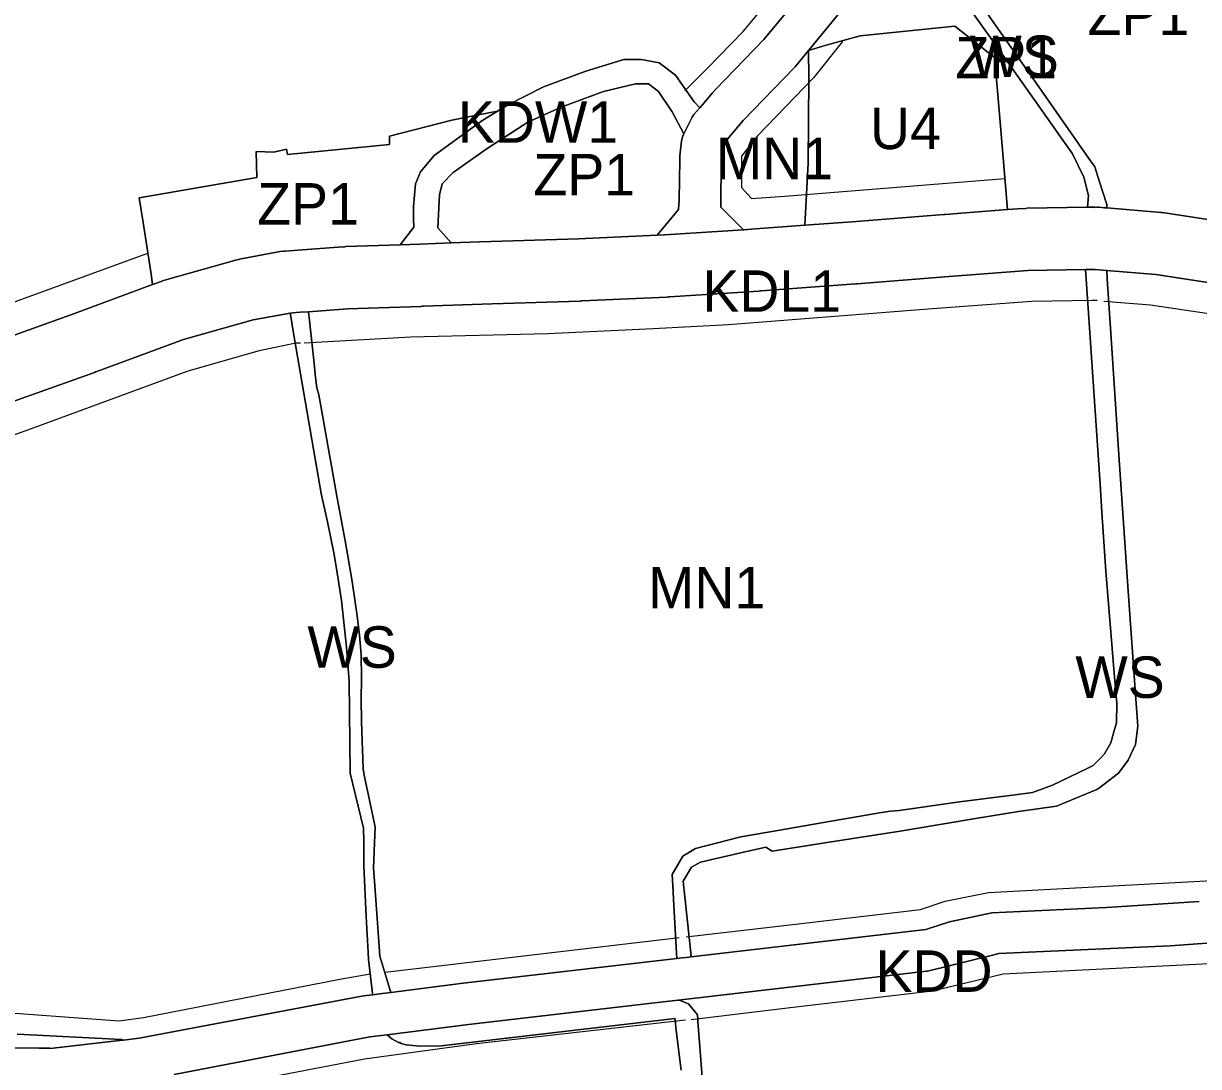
# Model space of a CAD drawing. Extents: x -284239 to -281592, y 34477 to 37267.
# Drawn here: x -282826.9 to -282543.7, y 34838 to 35089.5 of the extents above; entities that cross this region are included whole.
import ezdxf

# ---------------------------------------------------------------- set-up
doc = ezdxf.new("R2010")
doc.units = 0
for name, color, linetype in [('linie_rozgraniczajace', 7, 'Continuous'), ('linie_zabudowy_nieprzekraczalne', 7, 'Continuous'), ('oznaczenia_przeznaczen', 7, 'Continuous')]:
    doc.layers.add(name, color=color, linetype=linetype)

msp = doc.modelspace()

# ---------------------------------------------------------------- linework, layer by layer
at = {"layer": 'linie_rozgraniczajace'}
for points in [[(-282538.772, 35041.859), (-282551.853, 35043.871), (-282552.485, 35043.919), (-282552.668, 35043.964), (-282565.789, 35045.041), (-282565.808, 35045.885), (-282567.621, 35051.609), (-282568.68, 35054.953), (-282570.111, 35056.996), (-282581.07, 35072.638), (-282596.617, 35094.828), (-282609.755, 35113.582), (-282611.572, 35116.175), (-282614.042, 35117.421), (-282613.08, 35119.3), (-282610.133, 35128.196), (-282610.093, 35128.446), (-282609.945, 35128.969), (-282609.48, 35131.862), (-282600.308, 35133.065), (-282582.987, 35130.277), (-282556.202, 35125.799), (-282541.458, 35123.137)], [(-282636.922, 35099.643), (-282648.507, 35085.628), (-282660.041, 35073.649), (-282660.748, 35072.912), (-282660.948, 35072.694), (-282662.897, 35070.406), (-282663.908, 35069.219), (-282665.305, 35070.667), (-282669.735, 35077.066), (-282673.673, 35080.019), (-282677.938, 35080.84), (-282682.204, 35080.84), (-282691.392, 35078.05), (-282701.564, 35074.277), (-282710.26, 35069.847), (-282712.69, 35068.377), (-282717.657, 35067.445), (-282723.695, 35066.188), (-282738.74, 35062.356), (-282738.74, 35060.369), (-282763.295, 35057.956), (-282763.579, 35059.233), (-282766.56, 35058.524), (-282770.818, 35058.666), (-282770.676, 35052.42), (-282799.063, 35047.453), (-282798.07, 35041.491), (-282796.151, 35029.084), (-282795.832, 35026.541), (-282814.671, 35019.595), (-282837.032, 35011.566)], [(-282668.901, 35047.034), (-282668.738, 35056.643), (-282668.728, 35057.133), (-282668.702, 35057.574), (-282668.467, 35059.747), (-282668.32, 35061.107), (-282667.968, 35062.483), (-282667.876, 35062.622), (-282667.844, 35062.76), (-282667.767, 35062.918), (-282666.029, 35066.484), (-282665.714, 35066.927), (-282665.341, 35067.537), (-282663.908, 35069.219), (-282662.897, 35070.406), (-282660.948, 35072.694), (-282660.748, 35072.912), (-282660.041, 35073.649), (-282648.507, 35085.628), (-282636.922, 35099.643)], [(-282601.055, 35096.293), (-282592.555, 35084.274), (-282574.041, 35058.096), (-282571.344, 35052.434), (-282570.211, 35048.055), (-282570.476, 35045.195), (-282585.089, 35044.976), (-282585.653, 35044.859), (-282586.085, 35044.928), (-282589.712, 35044.647), (-282591.028, 35060.038), (-282592.158, 35073.29), (-282592.877, 35081.302), (-282602.43, 35088.904), (-282625.235, 35086.541), (-282633.479, 35084.274), (-282637.707, 35082.998), (-282637.614, 35083.111), (-282629.078, 35093.436)], [(-282596.617, 35094.828), (-282581.07, 35072.638), (-282570.111, 35056.996), (-282568.68, 35054.953), (-282567.621, 35051.609), (-282565.808, 35045.885), (-282565.789, 35045.041), (-282566.389, 35045.09), (-282567.683, 35045.196), (-282568.152, 35045.216), (-282568.414, 35045.163), (-282568.715, 35045.221), (-282568.756, 35045.22), (-282570.476, 35045.195), (-282570.211, 35048.055), (-282571.344, 35052.434), (-282574.041, 35058.096), (-282592.555, 35084.274), (-282601.055, 35096.293)], [(-282629.078, 35093.436), (-282637.614, 35083.111), (-282637.707, 35082.998), (-282640.92, 35079.111), (-282641.166, 35078.838), (-282653.434, 35066.093), (-282657.317, 35061.535), (-282658.472, 35059.165), (-282658.736, 35056.724), (-282658.852, 35045.263), (-282653.355, 35039.783), (-282672.385, 35038.548), (-282674.156, 35038.466), (-282669.063, 35044.635), (-282668.901, 35047.034)], [(-282837.032, 35011.566), (-282814.671, 35019.595), (-282795.832, 35026.541), (-282793.481, 35027.408), (-282793.409, 35027.421), (-282792.651, 35027.684), (-282775.484, 35032.544), (-282775.106, 35032.596), (-282774.505, 35032.774), (-282765.096, 35034.508), (-282764.222, 35034.588), (-282763.97, 35034.648), (-282750.06, 35035.661), (-282749.715, 35035.606), (-282749.253, 35035.706), (-282736.104, 35036.152), (-282731.441, 35036.31), (-282723.81, 35036.586), (-282714.78, 35036.912), (-282714.537, 35036.868), (-282714.25, 35036.93), (-282693.162, 35037.592), (-282674.156, 35038.466), (-282672.385, 35038.548), (-282653.355, 35039.783), (-282650.478, 35039.97), (-282638.574, 35040.847), (-282627.184, 35041.686), (-282605.073, 35043.458), (-282604.857, 35043.467), (-282604.806, 35043.479), (-282589.712, 35044.647), (-282586.085, 35044.928), (-282585.653, 35044.859), (-282585.089, 35044.976), (-282570.476, 35045.195), (-282568.756, 35045.22), (-282568.715, 35045.221), (-282568.414, 35045.163), (-282568.152, 35045.216), (-282567.683, 35045.196), (-282566.389, 35045.09), (-282565.789, 35045.041), (-282552.668, 35043.964), (-282552.485, 35043.919), (-282551.853, 35043.871), (-282538.772, 35041.859)], [(-282540.909, 35027.007), (-282553.966, 35029.016), (-282565.817, 35029.989), (-282566.718, 35030.063), (-282568.599, 35030.217), (-282568.758, 35030.214), (-282570.941, 35030.182), (-282584.867, 35029.973), (-282603.835, 35028.505), (-282625.96, 35026.732), (-282626.204, 35026.722), (-282626.257, 35026.709), (-282649.117, 35025.025), (-282649.349, 35025.063), (-282649.679, 35024.986), (-282671.197, 35023.589), (-282671.474, 35023.635), (-282671.842, 35023.553), (-282692.252, 35022.614), (-282692.528, 35022.662), (-282692.863, 35022.59), (-282713.987, 35021.927), (-282730.638, 35021.325), (-282730.872, 35021.367), (-282731.148, 35021.307), (-282748.823, 35020.707), (-282758.255, 35020.02), (-282760.232, 35019.876), (-282761.234, 35019.803), (-282762.663, 35019.699), (-282762.669, 35019.698), (-282771.569, 35018.058), (-282788.356, 35013.306), (-282809.302, 35005.583), (-282809.616, 35005.527), (-282809.83, 35005.391), (-282832.188, 34997.363)], [(-282543.51, 34877.775), (-282565.868, 34876.32), (-282593.517, 34874.997), (-282603.703, 34872.88), (-282609.448, 34870.987), (-282665.966, 34864.424), (-282665.984, 34864.6), (-282667.9, 34882.68), (-282665.91, 34886.04), (-282663.78, 34887.28), (-282653.67, 34889.59), (-282648.01, 34890.89), (-282646.44, 34889.88), (-282632.697, 34892.056), (-282615.62, 34894.76), (-282612.73, 34895.236), (-282597.435, 34897.755), (-282587.087, 34899.459), (-282577.95, 34900.8), (-282570.905, 34903.648), (-282568.18, 34904.75), (-282567.496, 34905.226), (-282562.992, 34908.709), (-282560.66, 34911.84), (-282558.87, 34915.67), (-282558.32, 34920.09), (-282558.942, 34928.854), (-282560.711, 34953.781), (-282561.94, 34971.307), (-282562.798, 34984.257), (-282564.898, 35016.044), (-282565.681, 35027.927), (-282565.817, 35029.989), (-282553.966, 35029.016), (-282540.909, 35027.007)], [(-282832.188, 34997.363), (-282809.83, 35005.391), (-282809.616, 35005.527), (-282809.302, 35005.583), (-282788.356, 35013.306), (-282771.569, 35018.058), (-282762.669, 35019.698), (-282762.663, 35019.699), (-282762.6, 35019.32), (-282761.662, 35013.864), (-282758.538, 34995.679), (-282755.19, 34976.18), (-282753.668, 34969.325), (-282752.02, 34961.45), (-282751.305, 34957.045), (-282750.319, 34950.339), (-282749.055, 34939.138), (-282748.417, 34930.909), (-282748.16, 34908.75), (-282746.241, 34900.76), (-282744.97, 34895.47), (-282744.941, 34892.203), (-282744.89, 34886.34), (-282744.301, 34874.157), (-282743.88, 34865.459), (-282743.8, 34863.81), (-282742.78, 34855.598), (-282742.739, 34855.269), (-282744.977, 34854.985), (-282799.031, 34844.77), (-282802.811, 34844.343), (-282803.33, 34844.5), (-282828.459, 34845.767)], [(-282838.174, 34842.487), (-282823.206, 34842.374), (-282820.965, 34842.357), (-282820.58, 34842.354), (-282820.527, 34842.344), (-282804.567, 34844.145), (-282802.811, 34844.343), (-282799.031, 34844.77), (-282744.977, 34854.985), (-282742.739, 34855.269), (-282740.517, 34855.552), (-282739.753, 34855.649), (-282738.383, 34855.823), (-282720.918, 34858.043), (-282669.438, 34864.021), (-282668.271, 34864.156), (-282667.163, 34864.285), (-282665.966, 34864.424), (-282609.448, 34870.987), (-282603.703, 34872.88), (-282593.517, 34874.997), (-282565.868, 34876.32), (-282543.51, 34877.775)], [(-282538.351, 34867.985), (-282550.522, 34867.059), (-282591.797, 34865.207), (-282592.727, 34865.009), (-282608.995, 34860.974), (-282609.061, 34860.999), (-282609.222, 34860.946), (-282669.118, 34853.991), (-282672.028, 34853.653), (-282719.71, 34848.116), (-282739.297, 34845.626), (-282743.417, 34845.102), (-282790.654, 34836.076)], [(-282662.112, 34819.789), (-282663.971, 34843.747), (-282664.365, 34848.828), (-282664.406, 34849.352), (-282664.49, 34850.44), (-282666.626, 34853.078), (-282668.87, 34853.94), (-282669.118, 34853.991), (-282609.222, 34860.946), (-282609.061, 34860.999), (-282608.995, 34860.974), (-282592.727, 34865.009), (-282591.797, 34865.207), (-282550.522, 34867.059), (-282538.351, 34867.985)], [(-282668.44, 34837.11), (-282669.71, 34847.3), (-282669.861, 34849.523), (-282726.25, 34842.984), (-282731.432, 34842.906), (-282734.73, 34843.22), (-282735.908, 34843.534), (-282736.201, 34843.729), (-282736.573, 34843.782), (-282738.115, 34844.655), (-282739.297, 34845.626), (-282719.71, 34848.116), (-282672.028, 34853.653), (-282669.118, 34853.991), (-282668.87, 34853.94), (-282666.626, 34853.078), (-282664.49, 34850.44), (-282664.406, 34849.352), (-282664.365, 34848.828), (-282663.971, 34843.747), (-282662.112, 34819.789)], [(-282790.654, 34836.076), (-282743.417, 34845.102), (-282739.297, 34845.626), (-282738.115, 34844.655), (-282736.573, 34843.782), (-282736.201, 34843.729), (-282735.908, 34843.534), (-282734.73, 34843.22), (-282731.432, 34842.906), (-282726.25, 34842.984), (-282669.861, 34849.523), (-282669.71, 34847.3), (-282668.44, 34837.11)], [(-282828.459, 34845.767), (-282803.33, 34844.5), (-282802.811, 34844.343), (-282804.567, 34844.145), (-282820.527, 34842.344), (-282820.58, 34842.354), (-282820.965, 34842.357), (-282823.206, 34842.374), (-282838.174, 34842.487)]]:
    msp.add_lwpolyline(points, dxfattribs=at)
for points in [[(-282638.574, 35040.847), (-282637.819, 35055.878), (-282637.614, 35076.32), (-282637.707, 35082.998), (-282633.479, 35084.274), (-282625.235, 35086.541), (-282602.43, 35088.904), (-282592.877, 35081.302), (-282592.158, 35073.29), (-282591.028, 35060.038), (-282589.712, 35044.647), (-282604.806, 35043.479), (-282604.857, 35043.467), (-282605.073, 35043.458), (-282627.184, 35041.686)], [(-282658.852, 35045.263), (-282658.736, 35056.724), (-282658.472, 35059.165), (-282657.317, 35061.535), (-282653.434, 35066.093), (-282641.166, 35078.838), (-282640.92, 35079.111), (-282637.707, 35082.998), (-282637.614, 35076.32), (-282637.819, 35055.878), (-282638.574, 35040.847), (-282650.478, 35039.97), (-282653.355, 35039.783)], [(-282736.104, 35036.152), (-282732.845, 35040.389), (-282732.901, 35042.448), (-282732.901, 35045.401), (-282732.408, 35050.815), (-282731.26, 35053.769), (-282727.979, 35057.706), (-282716.494, 35066.074), (-282712.69, 35068.377), (-282710.26, 35069.847), (-282701.564, 35074.277), (-282691.392, 35078.05), (-282682.204, 35080.84), (-282677.938, 35080.84), (-282673.673, 35080.019), (-282669.735, 35077.066), (-282665.305, 35070.667), (-282663.908, 35069.219), (-282665.341, 35067.537), (-282665.714, 35066.927), (-282666.029, 35066.484), (-282667.767, 35062.918), (-282670.555, 35068.206), (-282673.837, 35073.128), (-282676.298, 35074.933), (-282679.415, 35074.933), (-282687.126, 35073.128), (-282697.298, 35069.355), (-282705.338, 35065.745), (-282715.182, 35059.347), (-282723.385, 35053.605), (-282726.01, 35050.815), (-282726.666, 35048.19), (-282727.07, 35040.278), (-282723.81, 35036.586), (-282731.441, 35036.31)], [(-282727.07, 35040.278), (-282726.666, 35048.19), (-282726.01, 35050.815), (-282723.385, 35053.605), (-282715.182, 35059.347), (-282705.338, 35065.745), (-282697.298, 35069.355), (-282687.126, 35073.128), (-282679.415, 35074.933), (-282676.298, 35074.933), (-282673.837, 35073.128), (-282670.555, 35068.206), (-282667.767, 35062.918), (-282667.844, 35062.76), (-282667.876, 35062.622), (-282667.968, 35062.483), (-282668.32, 35061.107), (-282668.467, 35059.747), (-282668.702, 35057.574), (-282668.728, 35057.133), (-282668.738, 35056.643), (-282668.901, 35047.034), (-282669.063, 35044.635), (-282674.156, 35038.466), (-282693.162, 35037.592), (-282714.25, 35036.93), (-282714.537, 35036.868), (-282714.78, 35036.912), (-282723.81, 35036.586)], [(-282799.063, 35047.453), (-282770.676, 35052.42), (-282770.818, 35058.666), (-282766.56, 35058.524), (-282763.579, 35059.233), (-282763.295, 35057.956), (-282738.74, 35060.369), (-282738.74, 35062.356), (-282723.695, 35066.188), (-282717.657, 35067.445), (-282712.69, 35068.377), (-282716.494, 35066.074), (-282727.979, 35057.706), (-282731.26, 35053.769), (-282732.408, 35050.815), (-282732.901, 35045.401), (-282732.901, 35042.448), (-282732.845, 35040.389), (-282736.104, 35036.152), (-282749.253, 35035.706), (-282749.715, 35035.606), (-282750.06, 35035.661), (-282763.97, 35034.648), (-282764.222, 35034.588), (-282765.096, 35034.508), (-282774.505, 35032.774), (-282775.106, 35032.596), (-282775.484, 35032.544), (-282792.651, 35027.684), (-282793.409, 35027.421), (-282793.481, 35027.408), (-282795.832, 35026.541), (-282796.151, 35029.084), (-282798.07, 35041.491)], [(-282758.255, 35020.02), (-282748.823, 35020.707), (-282731.148, 35021.307), (-282730.872, 35021.367), (-282730.638, 35021.325), (-282713.987, 35021.927), (-282692.863, 35022.59), (-282692.528, 35022.662), (-282692.252, 35022.614), (-282671.842, 35023.553), (-282671.474, 35023.635), (-282671.197, 35023.589), (-282649.679, 35024.986), (-282649.349, 35025.063), (-282649.117, 35025.025), (-282626.257, 35026.709), (-282626.204, 35026.722), (-282625.96, 35026.732), (-282603.835, 35028.505), (-282584.867, 35029.973), (-282570.941, 35030.182), (-282570.225, 35019.65), (-282568.304, 34991.394), (-282567.421, 34978.411), (-282566.961, 34971.653), (-282565.996, 34957.473), (-282564.812, 34942.721), (-282563.916, 34931.87), (-282563.4, 34925.63), (-282563.48, 34920.87), (-282564.1, 34918.676), (-282564.85, 34916.02), (-282566.34, 34913.35), (-282567.327, 34912.356), (-282569.09, 34910.58), (-282570.55, 34909.872), (-282574.72, 34907.851), (-282578.87, 34905.84), (-282583.7, 34904.07), (-282587.9, 34903.48), (-282601.27, 34901.79), (-282615.83, 34899.75), (-282617.925, 34899.519), (-282620.562, 34899.138), (-282625.671, 34898.257), (-282632.763, 34897.034), (-282645.074, 34894.912), (-282654.02, 34893.37), (-282664.93, 34890.51), (-282668.01, 34888.71), (-282670.59, 34884.26), (-282670.437, 34881.582), (-282670.167, 34876.837), (-282669.512, 34865.329), (-282669.438, 34864.021), (-282720.918, 34858.043), (-282738.383, 34855.823), (-282741.05, 34864.58), (-282741.293, 34868.019), (-282741.694, 34873.707), (-282742.255, 34881.655), (-282742.55, 34885.83), (-282742.328, 34891.887), (-282742.19, 34895.67), (-282742.678, 34898.024), (-282743.151, 34900.308), (-282743.859, 34903.727), (-282744.707, 34907.821), (-282745.09, 34909.67), (-282745.172, 34912.223), (-282745.307, 34916.398), (-282745.462, 34921.208), (-282745.513, 34926.534), (-282745.443, 34931.566), (-282745.585, 34937.299), (-282745.941, 34942.023), (-282746.539, 34946.693), (-282747.703, 34954.966), (-282748.846, 34961.511), (-282749.421, 34964.74), (-282749.891, 34967.34), (-282751.374, 34975.55), (-282752.598, 34982.331), (-282753.573, 34987.729), (-282754.808, 34994.562), (-282755.79, 35000), (-282756.22, 35001.69), (-282756.55, 35004.18), (-282756.906, 35007.489), (-282758.029, 35017.923)], [(-282670.59, 34884.26), (-282668.01, 34888.71), (-282664.93, 34890.51), (-282654.02, 34893.37), (-282645.074, 34894.912), (-282632.763, 34897.034), (-282625.671, 34898.257), (-282620.562, 34899.138), (-282617.925, 34899.519), (-282615.83, 34899.75), (-282601.27, 34901.79), (-282587.9, 34903.48), (-282583.7, 34904.07), (-282578.87, 34905.84), (-282574.72, 34907.851), (-282570.55, 34909.872), (-282569.09, 34910.58), (-282567.327, 34912.356), (-282566.34, 34913.35), (-282564.85, 34916.02), (-282564.1, 34918.676), (-282563.48, 34920.87), (-282563.4, 34925.63), (-282563.916, 34931.87), (-282564.812, 34942.721), (-282565.996, 34957.473), (-282566.961, 34971.653), (-282567.421, 34978.411), (-282568.304, 34991.394), (-282570.225, 35019.65), (-282570.941, 35030.182), (-282568.758, 35030.214), (-282568.599, 35030.217), (-282566.718, 35030.063), (-282565.817, 35029.989), (-282565.681, 35027.927), (-282564.898, 35016.044), (-282562.798, 34984.257), (-282561.94, 34971.307), (-282560.711, 34953.781), (-282558.942, 34928.854), (-282558.32, 34920.09), (-282558.87, 34915.67), (-282560.66, 34911.84), (-282562.992, 34908.709), (-282567.496, 34905.226), (-282568.18, 34904.75), (-282570.905, 34903.648), (-282577.95, 34900.8), (-282587.087, 34899.459), (-282597.435, 34897.755), (-282612.73, 34895.236), (-282615.62, 34894.76), (-282632.697, 34892.056), (-282646.44, 34889.88), (-282648.01, 34890.89), (-282653.67, 34889.59), (-282663.78, 34887.28), (-282665.91, 34886.04), (-282667.9, 34882.68), (-282665.984, 34864.6), (-282665.966, 34864.424), (-282667.163, 34864.285), (-282668.271, 34864.156), (-282669.438, 34864.021), (-282669.512, 34865.329), (-282670.167, 34876.837), (-282670.437, 34881.582)], [(-282762.663, 35019.699), (-282761.234, 35019.803), (-282760.232, 35019.876), (-282758.255, 35020.02), (-282758.029, 35017.923), (-282756.906, 35007.489), (-282756.55, 35004.18), (-282756.22, 35001.69), (-282755.79, 35000), (-282754.808, 34994.562), (-282753.573, 34987.729), (-282752.598, 34982.331), (-282751.374, 34975.55), (-282749.891, 34967.34), (-282749.421, 34964.74), (-282748.846, 34961.511), (-282747.703, 34954.966), (-282746.539, 34946.693), (-282745.941, 34942.023), (-282745.585, 34937.299), (-282745.443, 34931.566), (-282745.513, 34926.534), (-282745.462, 34921.208), (-282745.307, 34916.398), (-282745.172, 34912.223), (-282745.09, 34909.67), (-282744.707, 34907.821), (-282743.859, 34903.727), (-282743.151, 34900.308), (-282742.678, 34898.024), (-282742.19, 34895.67), (-282742.328, 34891.887), (-282742.55, 34885.83), (-282742.255, 34881.655), (-282741.694, 34873.707), (-282741.293, 34868.019), (-282741.05, 34864.58), (-282738.383, 34855.823), (-282739.753, 34855.649), (-282740.517, 34855.552), (-282742.739, 34855.269), (-282742.78, 34855.598), (-282743.8, 34863.81), (-282743.88, 34865.459), (-282744.301, 34874.157), (-282744.89, 34886.34), (-282744.941, 34892.203), (-282744.97, 34895.47), (-282746.241, 34900.76), (-282748.16, 34908.75), (-282748.417, 34930.909), (-282749.055, 34939.138), (-282750.319, 34950.339), (-282751.305, 34957.045), (-282752.02, 34961.45), (-282753.668, 34969.325), (-282755.19, 34976.18), (-282758.538, 34995.679), (-282761.662, 35013.864), (-282762.6, 35019.32)]]:
    msp.add_lwpolyline(points, close=True, dxfattribs=at)
at = {"layer": 'linie_zabudowy_nieprzekraczalne'}
for points in [[(-282667.542, 35073.284), (-282662.171, 35078.638), (-282653.44, 35087.633), (-282640.872, 35102.781)], [(-282629.495, 35085.186), (-282636.507, 35076.455), (-282650, 35062.432), (-282653.837, 35057.537), (-282653.837, 35049.996), (-282651.456, 35047.351), (-282643.386, 35047.88), (-282590.337, 35052.113)], [(-282922.257, 34988.15), (-282884.289, 35002.107), (-282832.431, 35021.157), (-282796.977, 35034.121)], [(-282568.112, 35022.744), (-282569.302, 35022.744), (-282583.854, 35022.48), (-282607.799, 35020.694), (-282657.012, 35016.857), (-282675.136, 35015.865), (-282700.536, 35014.674), (-282733.609, 35013.881), (-282759.274, 35012.425)], [(-282488.207, 35011.632), (-282555.279, 35021.554), (-282566.524, 35022.48)], [(-282760.2, 35012.425), (-282761.258, 35012.425), (-282770.121, 35010.573), (-282787.319, 35005.679), (-282824.229, 34992.119), (-282852.01, 34982.064), (-282886.935, 34969.034), (-282914.055, 34959.112), (-282933.37, 34950.777), (-282949.774, 34939.731), (-282981.656, 34913.008), (-282982.847, 34904.012), (-282977.026, 34875.371), (-282973.719, 34848.516), (-282969.882, 34844.018), (-282955.462, 34843.886), (-282925.172, 34849.266), (-282910.356, 34849.663), (-282867.229, 34849.927), (-282831.245, 34850.986), (-282803.861, 34849.001), (-282798.043, 34849.821), (-282750.679, 34859.055), (-282743.36, 34860.31)], [(-282667.203, 34869.242), (-282640.877, 34872.285), (-282610.714, 34875.856), (-282604.761, 34877.841), (-282594.31, 34879.958), (-282544.833, 34882.603), (-282511.231, 34884.455)], [(-282215.294, 34843.842), (-282203.388, 34874.534), (-282203.917, 34876.253), (-282214.632, 34878.767), (-282226.142, 34880.619), (-282235.931, 34881.677), (-282259.347, 34882.868), (-282288.187, 34883.133), (-282346.395, 34878.767), (-282376.826, 34873.108), (-282394.153, 34870.829), (-282431.455, 34865.663), (-282504.484, 34864.744), (-282524.196, 34864.082), (-282533.059, 34863.156), (-282590.738, 34860.246), (-282607.804, 34856.145), (-282640.745, 34852.308), (-282666.012, 34849.266)], [(-282739.788, 34860.695), (-282668.923, 34869.11)], [(-282667.335, 34849.133), (-282717.739, 34843.445), (-282744.726, 34839.741), (-282787.849, 34831.45)]]:
    msp.add_lwpolyline(points, dxfattribs=at)

# ---------------------------------------------------------------- texts
at = {"layer": 'oznaczenia_przeznaczen'}
for s, p in [('ZP1', (-282570.436, 35086.737)), ('ZP1', (-282602.301, 35076.302)), ('WS', (-282598.893, 35076.617)), ('KDW1', (-282722.223, 35060.745)), ('U4', (-282622.879, 35059.232)), ('MN1', (-282660.027, 35051.965)), ('ZP1', (-282704.027, 35048.067)), ('ZP1', (-282770.62, 35041.029)), ('KDL1', (-282663.305, 35019.986)), ('MN1', (-282676.375, 34948.467)), ('WS', (-282758.509, 34934.138)), ('WS', (-282573.37, 34926.87)), ('KDD', (-282621.568, 34855.974))]:
    msp.add_text(s, height=10, dxfattribs=at).set_placement(p)

doc.saveas('drawing.dxf')
